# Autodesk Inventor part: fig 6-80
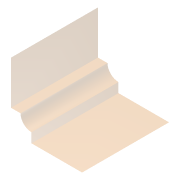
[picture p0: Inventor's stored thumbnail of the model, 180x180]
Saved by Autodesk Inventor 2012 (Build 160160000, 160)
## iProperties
Shininess: 64.0
Length Units: 11269
Angle Units: 11279
Time Units: 11290
Mass Units: 11283
Length Display Precision: 3
Angle Display Precision: 2
Compacted: True
Part Number: fig 6-80
Document SubType Name: Modeling
Created: 2003-10
Designer: Owner
Manufacturer: Standard
Standards Organization: Custom
Density: 1 g/cm^3
Material: Default
Density: 0.0
Volumn: 0.0
Area: 0.0
PropertySet Name: Model Information
Control State: 0
Master: False
Checked Out: False
Author: Owner
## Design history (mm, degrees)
node "Sketch1"
sketch "Sketch2"
  geometry: L1 (22.777, 31.862)-(22.777, 0.2); L2 (7.777, -14.8)-(-29.161, -14.8); A1 r 15 centre (7.777, 0.2) between (7.777, -14.8) and (22.777, 0.2)
  constraints: 4 end point, 2 point on circle, 2 tangent, 1 centre point, 1 perpendicular, 1 vertical
  dimensions: "d23" = 15 radius of A1
extrude_surface "ExtrusionSrf1" sketch "Sketch2" dims "d24" = 63.5, "d25" = 0
feature "OffsetSrf12" dims "d31" = 7, "d32" = 1
body "Solid1"
body "Srf1"
